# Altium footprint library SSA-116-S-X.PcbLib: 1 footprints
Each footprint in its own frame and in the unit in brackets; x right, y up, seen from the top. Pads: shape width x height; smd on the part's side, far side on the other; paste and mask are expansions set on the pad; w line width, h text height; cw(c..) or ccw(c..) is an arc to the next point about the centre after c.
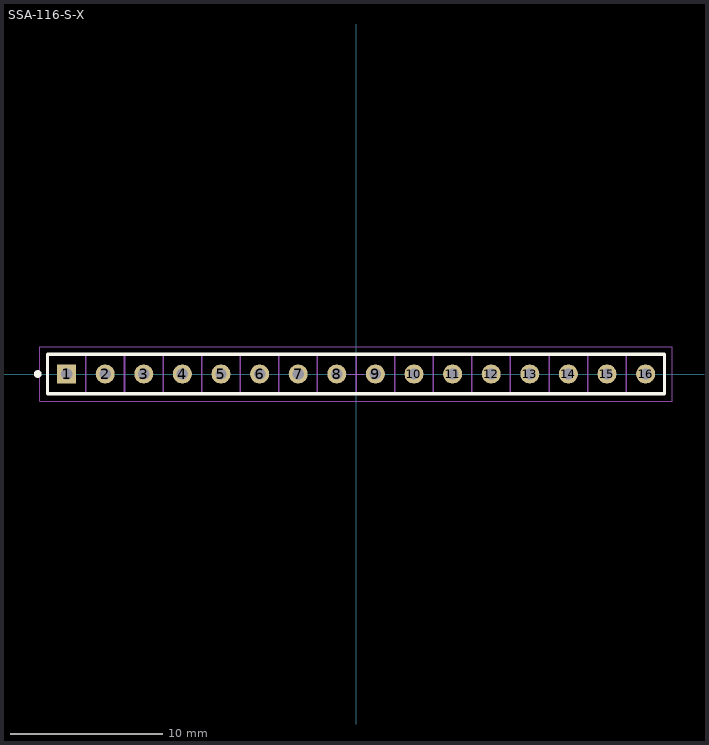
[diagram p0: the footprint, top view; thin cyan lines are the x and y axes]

## SSA-116-S-X [mm] "2.54mm pitch, terminal strip; single row"
height 5.84
pads (16):
  rect 1.25x1.25 / inner round 1.25 / far side rect 1.25x1.25 hole 0.75 mask+0: 1(-19.05,0)
  round 1.25 hole 0.75 mask+0: 2(-16.51,0) 3(-13.97,0) 4(-11.43,0) 5(-8.89,0) 6(-6.35,0) 7(-3.81,0) 8(-1.27,0) 9(1.27,0) 10(3.81,0) 11(6.35,0) 12(8.89,0) 13(11.43,0) 14(13.97,0) 15(16.51,0) 16(19.05,0)
Top Overlay:
  circle w0.25: c-20.95,0 r0.125
  lines w0.2: -20.3,-1.3 -20.3,1.3 20.3,1.3 20.3,-1.3 -20.3,-1.3
Mechanical 12:
  lines w0.001: -20.3,-1.3 -20.3,1.3 20.3,1.3 20.3,-1.3 -20.3,-1.3
Mechanical 13:
  lines w0.1: -17.78,-1.27 -17.78,1.27 ; -15.24,-1.27 -15.24,1.27 ; -12.7,-1.27 -12.7,1.27 ; -10.16,-1.27 -10.16,1.27 ; -7.62,-1.27 -7.62,1.27 ; -5.08,-1.27 -5.08,1.27 ; -2.54,-1.27 -2.54,1.27 ; 0,-1.27 0,1.27 ; 2.54,-1.27 2.54,1.27 ; 5.08,-1.27 5.08,1.27 ; 7.62,-1.27 7.62,1.27 ; 10.16,-1.27 10.16,1.27 ; 12.7,-1.27 12.7,1.27 ; 15.24,-1.27 15.24,1.27 ; 17.78,-1.27 17.78,1.27 ; -20.3,-1.3 -20.3,1.3 20.3,1.3 20.3,-1.3 -20.3,-1.3
  text ".Designator" at 0,-0.127 h1.52
Mechanical 15:
  lines w0.05: -0.5,0 0.5,0 ; 0,-0.5 0,0.5 ; -20.8,-1.8 -20.8,1.8 20.8,1.8 20.8,-1.8 -20.8,-1.8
